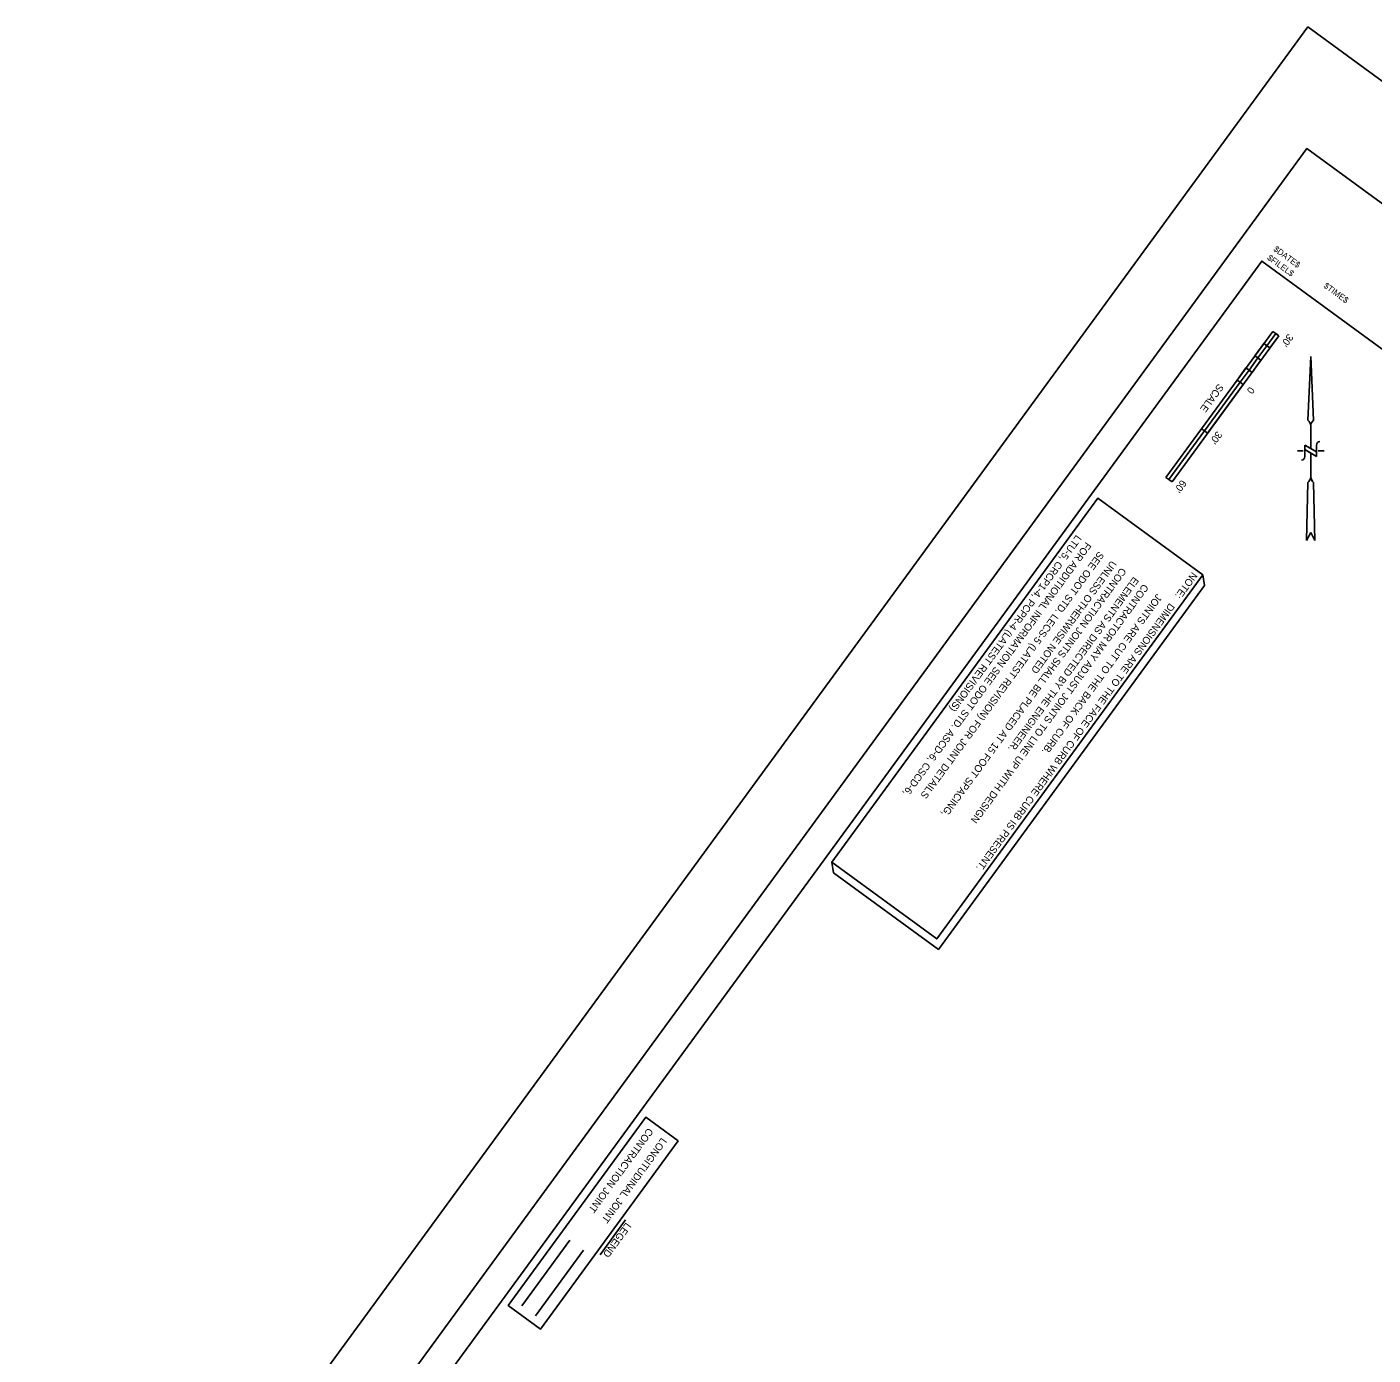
# Model space of a CAD drawing. Extents: x 2149779 to 2150997, y 143260 to 144556.
# Drawn here: x 2149779 to 2150449, y 143896 to 144556 of the extents above; entities that cross this region are included whole.
import ezdxf

# ---------------------------------------------------------------- set-up
doc = ezdxf.new("R2010")
doc.units = 0
for name, color, linetype in [('PR_Align_1_Leader', 7, 'Continuous'), ('PR_Align_1_PI_Curve', 7, 'Continuous'), ('PR_Align_Ramp_A_PI_Curve', 7, 'Continuous'), ('PR_Align_Ramp_B_PC', 7, 'Continuous'), ('PR_Align_Ramp_B_PI', 7, 'Continuous'), ('PR_Align_Ramp_G', 7, 'Continuous'), ('PR_Align_Ramp_G_Leader', 7, 'Continuous'), ('PR_Align_Ramp_G_Txt', 7, 'Continuous'), ('PR_Align_Ramp_L_Txt', 7, 'Continuous'), ('PR_Align_Service_B_PC', 7, 'Continuous')]:
    doc.layers.add(name, color=color, linetype=linetype)

msp = doc.modelspace()

# ---------------------------------------------------------------- linework, layer by layer
at = {"layer": 'PR_Align_1_PI_Curve'}
msp.add_line((2150076.74, 143962.87), (2150063.98, 143945.43), dxfattribs=at)
for points in [[(2150363.97, 144283.78), (2150231.52, 144102.61), (2150179.3, 144140.79), (2150311.75, 144321.95)], [(2150102.92, 144002.2), (2150034.45, 143908.54), (2150018.35, 143920.32), (2150086.82, 144013.97)]]:
    msp.add_lwpolyline(points, close=True, dxfattribs=at)
msp.add_lwpolyline([(2150363.97, 144283.78), (2150364.78, 144278.54), (2150232.33, 144097.37), (2150180.11, 144135.55), (2150179.3, 144140.79)], dxfattribs=at)
at = {"layer": 'PR_Align_Ramp_A_PI_Curve'}
msp.add_lwpolyline([(2150948.48, 144106.41), (2150346.5, 143282.99), (2149813.7, 143672.51), (2150415.68, 144495.93)], close=True, dxfattribs=at)
at = {"layer": 'PR_Align_Ramp_B_PC'}
for p, q in [((2150398.69, 144404.91), (2150345.58, 144332.26)), ((2150401.72, 144402.7), (2150348.6, 144330.04)), ((2150400.21, 144403.81), (2150395.78, 144397.75)), ((2150400.21, 144403.81), (2150395.78, 144397.75)), ((2150397.29, 144396.64), (2150401.72, 144402.7)), ((2150401.72, 144402.7), (2150398.69, 144404.91)), ((2150401.72, 144402.7), (2150400.21, 144403.81)), ((2150394.27, 144398.86), (2150389.84, 144392.8)), ((2150392.87, 144390.59), (2150389.84, 144392.8)), ((2150392.87, 144390.59), (2150389.84, 144392.8)), ((2150389.84, 144392.8), (2150391.35, 144391.7)), ((2150395.78, 144397.75), (2150391.35, 144391.7)), ((2150391.35, 144391.7), (2150395.78, 144397.75)), ((2150397.29, 144396.64), (2150394.27, 144398.86)), ((2150395.78, 144397.75), (2150394.27, 144398.86)), ((2150395.78, 144397.75), (2150397.29, 144396.64)), ((2150385.41, 144386.75), (2150380.99, 144380.69)), ((2150386.93, 144385.64), (2150382.5, 144379.59)), ((2150382.5, 144379.59), (2150386.93, 144385.64)), ((2150388.44, 144384.53), (2150385.41, 144386.75)), ((2150386.93, 144385.64), (2150385.41, 144386.75)), ((2150391.35, 144391.7), (2150386.93, 144385.64)), ((2150391.35, 144391.7), (2150386.93, 144385.64)), ((2150386.93, 144385.64), (2150388.44, 144384.53)), ((2150388.44, 144384.53), (2150392.87, 144390.59)), ((2150392.87, 144390.59), (2150391.35, 144391.7)), ((2150382.5, 144379.59), (2150347.09, 144331.15)), ((2150382.5, 144379.59), (2150364.79, 144355.37)), ((2150380.99, 144380.69), (2150382.5, 144379.59)), ((2150380.99, 144380.69), (2150382.5, 144379.59)), ((2150382.5, 144379.59), (2150384.01, 144378.48)), ((2150384.01, 144378.48), (2150382.5, 144379.59)), ((2150366.31, 144354.26), (2150384.01, 144378.48)), ((2150363.28, 144356.48), (2150345.58, 144332.26)), ((2150347.09, 144331.15), (2150364.79, 144355.37)), ((2150363.28, 144356.48), (2150364.79, 144355.37)), ((2150364.79, 144355.37), (2150363.28, 144356.48)), ((2150364.79, 144355.37), (2150366.31, 144354.26)), ((2150364.79, 144355.37), (2150366.31, 144354.26)), ((2150347.09, 144331.15), (2150345.58, 144332.26)), ((2150345.58, 144332.26), (2150347.09, 144331.15)), ((2150348.6, 144330.04), (2150347.09, 144331.15))]:
    msp.add_line(p, q, dxfattribs=at)
at = {"layer": 'PR_Align_Ramp_B_PI'}
for p, q in [((2150416.17, 144360.67), (2150417.61, 144392.4)), ((2150417.61, 144392.4), (2150416.17, 144360.67)), ((2150417.61, 144392.4), (2150419.05, 144360.67)), ((2150419.05, 144360.67), (2150417.61, 144392.4)), ((2150417.61, 144346.63), (2150417.61, 144357.86)), ((2150413.87, 144345.48), (2150410.99, 144345.48)), ((2150420.49, 144344.91), (2150414.73, 144348.36)), ((2150414.73, 144348.36), (2150420.49, 144344.91)), ((2150414.73, 144348.36), (2150414.73, 144342.6)), ((2150417.61, 144346.63), (2150414.73, 144348.36)), ((2150414.73, 144348.36), (2150414.73, 144346.06)), ((2150420.49, 144342.6), (2150414.73, 144346.06)), ((2150420.49, 144344.91), (2150417.61, 144346.63)), ((2150420.49, 144348.36), (2150420.49, 144342.6)), ((2150424.23, 144345.48), (2150421.35, 144345.48)), ((2150417.61, 144332.53), (2150417.61, 144344.33)), ((2150420.49, 144342.6), (2150420.49, 144344.91)), ((2150415.59, 144300.87), (2150416.17, 144329.65)), ((2150416.17, 144329.65), (2150415.59, 144300.87)), ((2150419.62, 144300.87), (2150419.05, 144329.65)), ((2150419.62, 144300.87), (2150419.05, 144329.65)), ((2150415.59, 144300.87), (2150417.61, 144304.9)), ((2150415.59, 144300.87), (2150417.61, 144304.9)), ((2150417.61, 144304.9), (2150419.62, 144300.87)), ((2150417.61, 144304.9), (2150419.62, 144300.87))]:
    msp.add_line(p, q, dxfattribs=at)
for points in [[(2150414.73, 144346.06), (2150417.61, 144344.33), (2150420.49, 144342.6)], [(2150417.61, 144332.53), (2150417.61, 144332.53), (2150417.61, 144332.53)]]:
    msp.add_lwpolyline(points, dxfattribs=at)
for centre, radius, start, end in [((2150414.16, 144357.86), 3.45, 0, 54.38016), ((2150414.16, 144357.86), 3.45, 0, 54.38016), ((2150421.06, 144357.86), 3.45, 125.61984, 180), ((2150421.06, 144357.86), 3.45, 125.61984, 180), ((2150422.22, 144348.36), 1.73, 90, 180), ((2150413, 144342.6), 1.73, 270, 0), ((2150412.6, 144333.23), 5.06, 314.95671, 352.41889), ((2150412.6, 144333.23), 5.06, 314.95671, 352.059), ((2150422.62, 144333.23), 5.06, 187.58111, 225.04329), ((2150422.62, 144333.23), 5.06, 187.941, 225.04329)]:
    msp.add_arc(centre, radius, start, end, dxfattribs=at)
at = {"layer": 'PR_Align_Ramp_G'}
msp.add_line((2150364.78, 144278.54), (2150363.97, 144283.78), dxfattribs=at)
for points in [[(2150363.97, 144283.78), (2150231.52, 144102.61), (2150179.3, 144140.79)], [(2150179.3, 144140.79), (2150180.11, 144135.55), (2150232.33, 144097.37), (2150364.78, 144278.54)]]:
    msp.add_lwpolyline(points, dxfattribs=at)
at = {"layer": 'PR_Align_Ramp_G_Leader'}
msp.add_lwpolyline([(2150997.45, 144131.46), (2150360.06, 143259.6), (2149778.82, 143684.53), (2150416.22, 144556.39)], close=True, dxfattribs=at)
at = {"layer": 'PR_Align_Ramp_G_Txt'}
msp.add_lwpolyline([(2149835.55, 143676.97), (2150393.26, 144439.85), (2150901.85, 144068.04), (2150344.13, 143305.16)], close=True, dxfattribs=at)
at = {"layer": 'PR_Align_Ramp_L_Txt'}
msp.add_line((2150055.81, 143947.69), (2150031.95, 143915.06), dxfattribs=at)
at = {"layer": 'PR_Align_Service_B_PC'}
msp.add_lwpolyline([(2150049.01, 143952.67), (2150025.15, 143920.03)], dxfattribs=at)

# ---------------------------------------------------------------- texts
at = {"layer": 'PR_Align_1_Leader'}
for s, p in [('$DATE$', (2150398.8, 144445.27)), ('$FILEL$', (2150395.66, 144440.97)), ('$TIME$', (2150423.74, 144427.03))]:
    msp.add_text(s, height=3, rotation=323.83041, dxfattribs=at).set_placement(p)
at = {"layer": 'PR_Align_1_PI_Curve'}
for s, p in [('FOR ADDITIONAL INFORMATION SEE ODOT STD. ASCD-6, CSCD-6,', (2150305.82, 144300.33)), ('LTU-5, CRCP1-4, PCPR-4 (LATEST REVISIONS)', (2150300.96, 144303.88)), ('SEE ODOT STD. LECS-5 (LATEST REVISION) FOR JOINT DETAILS', (2150312.14, 144295.7)), ('CONTRACTION JOINTS SHALL BE PLACED AT 15 FOOT SPACING,', (2150323.23, 144287.6)), ('UNLESS OTHERWISE NOTED', (2150318.38, 144291.15)), ('CONTRACTOR MAY ADJUST JOINTS TO LINE UP WITH DESIGN', (2150334.3, 144279.51)), ('ELEMENTS AS DIRECTED BY THE ENGINEER.', (2150329.45, 144283.05)), ('NOTE:', (2150358.62, 144285.39)), ('JOINTS ARE CUT TO THE BACK OF CURB.', (2150341.03, 144274.59)), ('DIMENSIONS ARE TO THE FACE OF CURB WHERE CURB IS PRESENT.', (2150347.35, 144269.97)), ('CONTRACTION JOINT', (2150087.88, 144008.88)), ('LONGITUDINAL JOINT', (2150094.58, 144003.98)), ('LEGEND', (2150076.91, 143961.78))]:
    msp.add_text(s, height=3.6, rotation=233.83041, dxfattribs=at).set_placement(p)
at = {"layer": 'PR_Align_Ramp_B_PC'}
for s, p in [("30'", (2150406.39, 144404.01)), ('SCALE', (2150371.68, 144379.15)), ('0', (2150387.13, 144377.67)), ("30'", (2150370.98, 144355.57)), ("60'", (2150353.27, 144331.35))]:
    msp.add_text(s, height=3.6, rotation=233.83041, dxfattribs=at).set_placement(p)

doc.saveas('drawing.dxf')
